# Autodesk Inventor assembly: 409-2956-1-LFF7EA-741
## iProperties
Created: 2010-09
Part Number: 409-2956-1-LFF7EA-741
Document SubType Name: Weldment
Designer: S. Boerckel
Weld Material: Welded Steel Mild
Mass: 38238.7 g
Surface Area: 12509.7 cm^2
Volume: 4861.71 cm^3
Density: 7.86528 g/cm^3
Description: DISCHARGE SPOOL
Material: WELDMENT
SMR: =<MATERIAL>
Author: S. Boerckel
Revision Number: A
